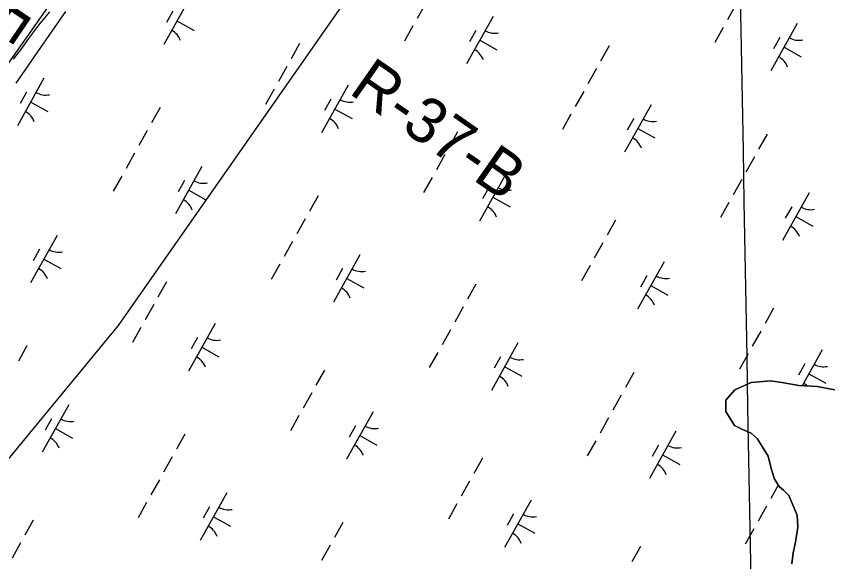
# Model space of a CAD drawing. Extents: x 3923531 to 3943530, y 207391 to 229799.
# Drawn here: x 3935013 to 3935760, y 216015 to 216516 of the extents above; entities that cross this region are included whole.
import ezdxf

# ---------------------------------------------------------------- set-up
doc = ezdxf.new("R2010")
doc.units = 0
for name, color, linetype in [('V-GRID-MAJR', 7, 'Continuous'), ('V-RIVR-EDGE', 7, 'Continuous'), ('V-RIVR-IDEN', 7, 'Continuous'), ('V-RIVR-RANG-IDEN', 7, 'Continuous'), ('V-RRAP-FSHR', 7, 'Continuous'), ('V-TOPO-SHOR', 7, 'Continuous'), ('V-UTIL-LINE', 7, 'Continuous'), ('V-WETL-SWMP', 7, 'Continuous')]:
    doc.layers.add(name, color=color, linetype=linetype)

msp = doc.modelspace()

# ---------------------------------------------------------------- linework, layer by layer
at = {"layer": 'V-GRID-MAJR'}
msp.add_spline([(3935779.93, 210874.81), (3935760.83, 211942.59), (3935652.4, 218002.59), (3935543.98, 224062.57), (3935501.82, 226418.85)], degree=3, dxfattribs=at)
at = {"layer": 'V-RIVR-EDGE'}
msp.add_lwpolyline([(3935045.25, 216529.63), (3934883.48, 216300.45)], dxfattribs=at)
at = {"layer": 'V-RRAP-FSHR'}
msp.add_lwpolyline([(3935012.7, 216454.9), (3935035.62, 216487.68), (3935058.48, 216520.8)], dxfattribs=at)
at = {"layer": 'V-TOPO-SHOR'}
msp.add_lwpolyline([(3935765.35, 216172.85), (3935749.03, 216175.81), (3935732.1, 216176.79), (3935718.37, 216179.12), (3935706.43, 216181.24), (3935688.27, 216179.63), (3935673.25, 216172.81), (3935665.17, 216163.33), (3935665.07, 216152.76), (3935672.91, 216140.12), (3935679.65, 216136.66), (3935688.38, 216132.98), (3935693.91, 216127.94), (3935698.62, 216120.71), (3935704.11, 216111.69), (3935706.79, 216100.49), (3935709.88, 216090.69), (3935714.39, 216083.67), (3935718.14, 216080.44), (3935722.88, 216075.81), (3935730.66, 216057.59), (3935731.15, 216046.42), (3935729.21, 216032.68), (3935727.12, 216022.93), (3935725.82, 216012.98)], dxfattribs=at)
at = {"layer": 'V-UTIL-LINE'}
msp.add_lwpolyline([(3939084.62, 223621.72), (3938057.71, 221140.48), (3938136.4, 220832.47), (3937591.63, 219695.21), (3936312.73, 217957.68), (3935106.6, 216231.89), (3934055.84, 214955.86), (3930691.13, 211497.88), (3930457.99, 211185.48)], dxfattribs=at)
at = {"layer": 'V-WETL-SWMP'}
for p, q in [((3935172.77, 216533.98), (3935148.38, 216490.33)), ((3935389.22, 216528.35), (3935381.42, 216514.39)), ((3935674.42, 216527.1), (3935666.62, 216513.13)), ((3935043.56, 216520.33), (3935033.27, 216508.28)), ((3935156.77, 216521.15), (3935150.91, 216510.68)), ((3935451.18, 216516.17), (3935426.8, 216472.51)), ((3935033.27, 216508.28), (3935024.17, 216496.01)), ((3935160.58, 216512.15), (3935176.29, 216503.37)), ((3935377.52, 216507.4), (3935369.71, 216493.43)), ((3935730.8, 216509.69), (3935706.42, 216466.04)), ((3935435.18, 216503.34), (3935429.33, 216492.86)), ((3935662.71, 216506.15), (3935654.91, 216492.18)), ((3935024.17, 216496.01), (3935017.7, 216486.71)), ((3935438.99, 216494.34), (3935454.7, 216485.56)), ((3935714.8, 216496.86), (3935708.95, 216486.39)), ((3935017.7, 216486.71), (3935010.02, 216477.02)), ((3935273.3, 216491.22), (3935265.5, 216477.25)), ((3935557.85, 216489.13), (3935550.04, 216475.17)), ((3935718.61, 216487.86), (3935734.32, 216479.08)), ((3935261.6, 216470.27), (3935253.8, 216456.3)), ((3935546.14, 216468.18), (3935538.34, 216454.21)), ((3935038.36, 216459.33), (3935013.98, 216415.68)), ((3935249.89, 216449.31), (3935242.09, 216435.35)), ((3935317.98, 216452.85), (3935293.6, 216409.2)), ((3935534.44, 216447.23), (3935526.63, 216433.26)), ((3935022.36, 216446.51), (3935016.51, 216436.03)), ((3935301.98, 216440.03), (3935296.13, 216429.55)), ((3935026.17, 216437.5), (3935041.88, 216428.73)), ((3935145.03, 216432.3), (3935137.22, 216418.33)), ((3935596.4, 216435.04), (3935572.01, 216391.39)), ((3935305.79, 216431.03), (3935321.5, 216422.25)), ((3935522.73, 216426.28), (3935514.93, 216412.31)), ((3935580.39, 216422.22), (3935574.54, 216411.74)), ((3935133.32, 216411.35), (3935125.52, 216397.38)), ((3935418.52, 216410.09), (3935410.71, 216396.13)), ((3935584.2, 216413.22), (3935599.92, 216404.44)), ((3935703.06, 216408.01), (3935695.26, 216394.04)), ((3935121.62, 216390.39), (3935113.81, 216376.43)), ((3935406.81, 216389.14), (3935399.01, 216375.17)), ((3935691.36, 216387.06), (3935683.55, 216373.09)), ((3935183.58, 216378.21), (3935159.19, 216334.55)), ((3935109.91, 216369.44), (3935102.11, 216355.47)), ((3935167.57, 216365.38), (3935161.72, 216354.9)), ((3935395.11, 216368.19), (3935387.3, 216354.22)), ((3935463.2, 216371.73), (3935438.81, 216328.08)), ((3935679.65, 216366.1), (3935671.85, 216352.14)), ((3935447.19, 216358.9), (3935441.34, 216348.43)), ((3935171.38, 216356.38), (3935187.1, 216347.6)), ((3935290.24, 216351.17), (3935282.44, 216337.21)), ((3935451, 216349.9), (3935466.72, 216341.12)), ((3935741.61, 216353.92), (3935717.23, 216310.27)), ((3935667.95, 216345.15), (3935660.14, 216331.18)), ((3935725.61, 216341.09), (3935719.76, 216330.62)), ((3935278.54, 216330.22), (3935270.73, 216316.25)), ((3935563.73, 216328.97), (3935555.93, 216315)), ((3935729.42, 216332.09), (3935745.13, 216323.31)), ((3935050.38, 216314.89), (3935025.99, 216271.24)), ((3935266.83, 216309.27), (3935259.03, 216295.3)), ((3935552.03, 216308.02), (3935544.22, 216294.05)), ((3935034.37, 216302.07), (3935028.52, 216291.59)), ((3935038.18, 216293.07), (3935053.9, 216284.29)), ((3935328.79, 216297.08), (3935304.41, 216253.43)), ((3935608.41, 216290.6), (3935584.02, 216246.95)), ((3935255.13, 216288.32), (3935247.32, 216274.35)), ((3935312.79, 216284.26), (3935306.94, 216273.78)), ((3935540.32, 216287.07), (3935532.52, 216273.1)), ((3935316.6, 216275.26), (3935332.31, 216266.48)), ((3935592.41, 216277.78), (3935586.56, 216267.3)), ((3935150.91, 216272.13), (3935143.11, 216258.17)), ((3935435.45, 216270.05), (3935427.65, 216256.08)), ((3935596.22, 216268.78), (3935611.93, 216260)), ((3935139.21, 216251.18), (3935131.4, 216237.21)), ((3935423.75, 216249.1), (3935415.95, 216235.13)), ((3935708.95, 216247.85), (3935701.14, 216233.88)), ((3935195.59, 216233.77), (3935171.2, 216190.12)), ((3935127.5, 216230.23), (3935119.7, 216216.26)), ((3935412.04, 216228.14), (3935404.24, 216214.18)), ((3935697.24, 216226.89), (3935689.44, 216212.93)), ((3935179.59, 216220.94), (3935173.74, 216210.47)), ((3935474, 216215.96), (3935449.62, 216172.31)), ((3935022.63, 216213.21), (3935014.83, 216199.24)), ((3935183.4, 216211.94), (3935199.11, 216203.16)), ((3935753.62, 216209.48), (3935735.26, 216176.6)), ((3935400.34, 216207.19), (3935392.54, 216193.22)), ((3935458, 216203.13), (3935452.15, 216192.66)), ((3935685.54, 216205.94), (3935677.73, 216191.97)), ((3935461.81, 216194.13), (3935477.53, 216185.35)), ((3935737.62, 216196.65), (3935731.77, 216186.18)), ((3935296.13, 216191.01), (3935288.32, 216177.04)), ((3935580.67, 216188.92), (3935572.86, 216174.96)), ((3935741.43, 216187.65), (3935757.14, 216178.88)), ((3935673.25, 216172.81), (3935688.27, 216179.63)), ((3935688.27, 216179.63), (3935706.43, 216181.24)), ((3935706.43, 216181.24), (3935718.37, 216179.12)), ((3935718.37, 216179.12), (3935732.1, 216176.79)), ((3935665.17, 216163.32), (3935673.25, 216172.81)), ((3935732.1, 216176.79), (3935749.03, 216175.81)), ((3935749.03, 216175.81), (3935765.35, 216172.85)), ((3935284.42, 216170.06), (3935276.62, 216156.09)), ((3935568.96, 216167.97), (3935561.16, 216154)), ((3935665.06, 216152.76), (3935665.17, 216163.32)), ((3935061.18, 216159.12), (3935036.8, 216115.47)), ((3935272.72, 216149.11), (3935264.91, 216135.14)), ((3935340.8, 216152.64), (3935316.42, 216108.99)), ((3935672.91, 216140.12), (3935665.06, 216152.76)), ((3935045.18, 216146.3), (3935039.33, 216135.82)), ((3935557.26, 216147.02), (3935549.45, 216133.05)), ((3935048.99, 216137.3), (3935064.71, 216128.52)), ((3935324.8, 216139.82), (3935318.95, 216129.34)), ((3935619.22, 216134.83), (3935594.83, 216091.18)), ((3935679.65, 216136.66), (3935672.91, 216140.12)), ((3935688.38, 216132.98), (3935679.65, 216136.66)), ((3935167.85, 216132.09), (3935160.05, 216118.12)), ((3935328.61, 216130.82), (3935344.33, 216122.04)), ((3935545.55, 216126.07), (3935537.75, 216112.1)), ((3935693.91, 216127.94), (3935688.38, 216132.98)), ((3935698.62, 216120.71), (3935693.91, 216127.94)), ((3935603.22, 216122.01), (3935597.36, 216111.53)), ((3935704.11, 216111.69), (3935698.62, 216120.71)), ((3935156.14, 216111.14), (3935148.34, 216097.17)), ((3935607.03, 216113.01), (3935622.74, 216104.23)), ((3935706.79, 216100.49), (3935704.11, 216111.69)), ((3935441.34, 216109.89), (3935433.54, 216095.92)), ((3935709.88, 216090.7), (3935706.79, 216100.49)), ((3935144.44, 216090.18), (3935136.64, 216076.22)), ((3935429.63, 216088.93), (3935421.83, 216074.97)), ((3935714.39, 216083.67), (3935709.88, 216090.7)), ((3935713.33, 216085.32), (3935706.37, 216072.88)), ((3935718.14, 216080.44), (3935714.39, 216083.67)), ((3935206.4, 216078), (3935182.01, 216034.35)), ((3935722.88, 216075.81), (3935718.14, 216080.44)), ((3935730.66, 216057.59), (3935722.88, 216075.81)), ((3935132.73, 216069.23), (3935124.93, 216055.26)), ((3935417.93, 216067.98), (3935410.13, 216054.01)), ((3935486.02, 216071.52), (3935461.63, 216027.87)), ((3935190.4, 216065.17), (3935184.54, 216054.7)), ((3935470.02, 216058.69), (3935464.16, 216048.22)), ((3935702.47, 216065.9), (3935694.67, 216051.93)), ((3935028.52, 216053.05), (3935020.72, 216039.08)), ((3935194.21, 216056.17), (3935209.92, 216047.39)), ((3935731.15, 216046.42), (3935730.66, 216057.59)), ((3935313.06, 216050.96), (3935305.26, 216037)), ((3935473.82, 216049.69), (3935489.54, 216040.92)), ((3935690.77, 216044.94), (3935682.96, 216030.98)), ((3935729.21, 216032.68), (3935731.15, 216046.42)), ((3935016.81, 216032.1), (3935009.01, 216018.13)), ((3935301.36, 216030.01), (3935293.55, 216016.04)), ((3935586.55, 216028.76), (3935578.75, 216014.79)), ((3935727.12, 216022.93), (3935729.21, 216032.68)), ((3935725.82, 216012.98), (3935727.12, 216022.93))]:
    msp.add_line(p, q, dxfattribs=at)
for centre, start, end in [((3935147.31, 216487.92), 20.03808, 61.58174), ((3935452.67, 216518.34), 240.03808, 281.58174), ((3935732.29, 216511.86), 240.03808, 281.58174), ((3935425.73, 216470.11), 20.03808, 61.58174), ((3935705.35, 216463.63), 20.03808, 61.58174), ((3935039.85, 216461.5), 240.03808, 281.58174), ((3935319.47, 216455.02), 240.03808, 281.58174), ((3935012.91, 216413.27), 20.03808, 61.58174), ((3935292.53, 216406.8), 20.03808, 61.58174), ((3935597.88, 216437.21), 240.03808, 281.58174), ((3935570.94, 216388.99), 20.03808, 61.58174), ((3935185.06, 216380.38), 240.03808, 281.58174), ((3935464.68, 216373.9), 240.03808, 281.58174), ((3935158.12, 216332.15), 20.03808, 61.58174), ((3935437.74, 216325.67), 20.03808, 61.58174), ((3935743.1, 216356.09), 240.03808, 281.58174), ((3935716.15, 216307.86), 20.03808, 61.58174), ((3935051.86, 216317.06), 240.03808, 281.58174), ((3935024.92, 216268.84), 20.03808, 61.58174), ((3935330.28, 216299.25), 240.03808, 281.58174), ((3935609.9, 216292.78), 240.03808, 281.58174), ((3935303.33, 216251.03), 20.03808, 61.58174), ((3935582.95, 216244.55), 20.03808, 61.58174), ((3935197.08, 216235.94), 240.03808, 281.58174), ((3935170.13, 216187.71), 20.03808, 61.58174), ((3935475.49, 216218.13), 240.03808, 281.58174), ((3935755.11, 216211.65), 240.03808, 281.58174), ((3935448.55, 216169.9), 20.03808, 61.58174), ((3935728.17, 216163.42), 47.04093, 61.58174), ((3935062.67, 216161.29), 240.03808, 281.58174), ((3935342.29, 216154.82), 240.03808, 281.58174), ((3935035.73, 216113.07), 20.03808, 61.58174), ((3935315.35, 216106.59), 20.03808, 61.58174), ((3935620.7, 216137.01), 240.03808, 281.58174), ((3935593.76, 216088.78), 20.03808, 61.58174), ((3935207.88, 216080.17), 240.03808, 281.58174), ((3935487.5, 216073.69), 240.03808, 281.58174), ((3935180.94, 216031.94), 20.03808, 61.58174), ((3935460.56, 216025.46), 20.03808, 61.58174)]:
    msp.add_arc(centre, 17.62, start, end, dxfattribs=at)

# ---------------------------------------------------------------- texts
at = {"layer": 'V-RIVR-IDEN'}
msp.add_text('Edge', height=42, rotation=235.91618, dxfattribs=at).set_placement((3934994.24, 216541.98))
at = {"layer": 'V-RIVR-RANG-IDEN'}
msp.add_text('R-37-B', height=41.5, rotation=325.10855, dxfattribs=at).set_placement((3935317.56, 216446.04))

doc.saveas('drawing.dxf')
